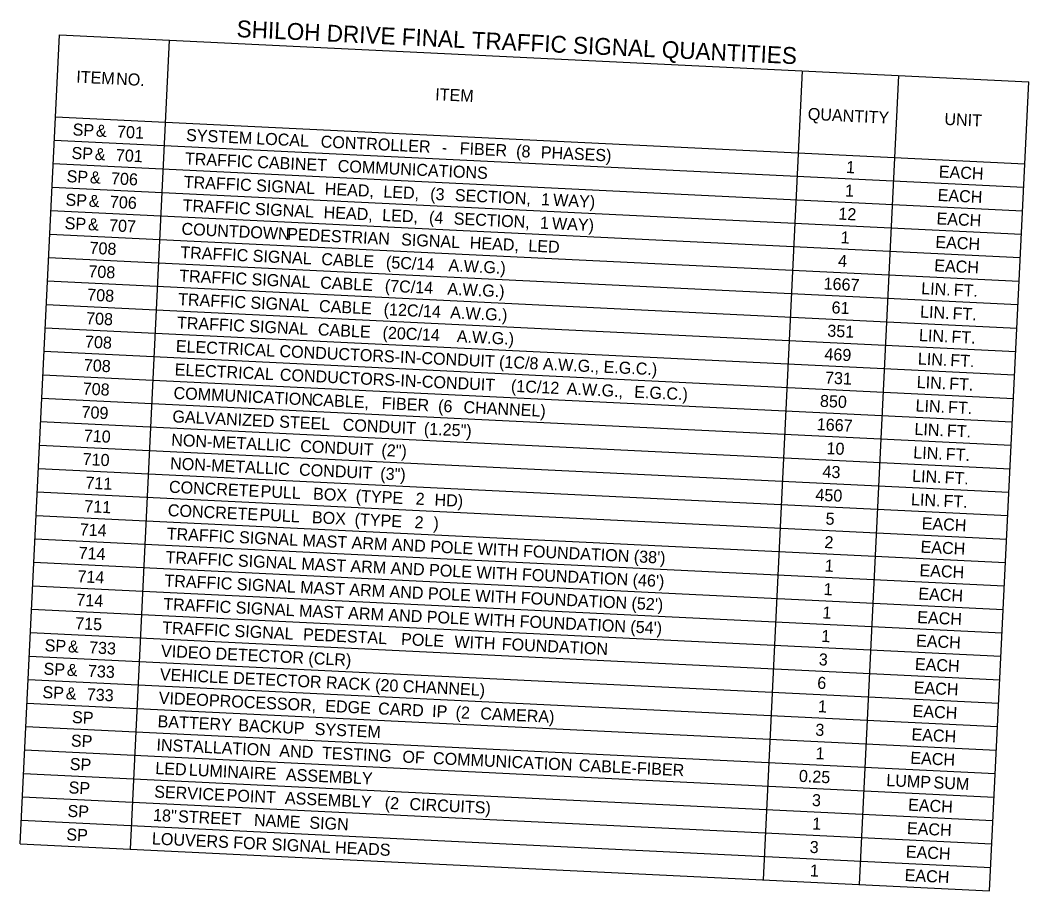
# Model space of a CAD drawing. Extents: x 661018 to 663325, y 642537 to 643074.
# Drawn here: x 661251.9 to 661454.9, y 642806.7 to 642981.8 of the extents above; entities that cross this region are included whole.
import ezdxf

# ---------------------------------------------------------------- set-up
doc = ezdxf.new("R2010")
doc.units = 0
doc.layers.add('R_Border Notes', color=7, linetype='Continuous')

msp = doc.modelspace()

# ---------------------------------------------------------------- linework, layer by layer
at = {"layer": 'R_Border Notes'}
for p, q in [((661251.88, 642816.15), (661259.78, 642978.89)), ((661259.78, 642978.89), (661454.87, 642969.42)), ((661274.05, 642815.08), (661281.95, 642977.81)), ((661401.45, 642808.89), (661409.35, 642971.63)), ((661420.79, 642807.95), (661428.69, 642970.69)), ((661446.97, 642806.68), (661454.87, 642969.42)), ((661258.98, 642962.38), (661454.07, 642952.91)), ((661258.75, 642957.66), (661453.84, 642948.19)), ((661258.52, 642952.95), (661453.61, 642943.47)), ((661258.29, 642948.23), (661453.38, 642938.76)), ((661258.06, 642943.51), (661453.15, 642934.04)), ((661257.83, 642938.79), (661452.92, 642929.32)), ((661257.6, 642934.08), (661452.69, 642924.6)), ((661257.37, 642929.36), (661452.46, 642919.89)), ((661257.14, 642924.64), (661452.24, 642915.17)), ((661256.92, 642919.93), (661452.01, 642910.45)), ((661256.69, 642915.21), (661451.78, 642905.74)), ((661256.46, 642910.49), (661451.55, 642901.02)), ((661256.23, 642905.78), (661451.32, 642896.3)), ((661256, 642901.06), (661451.09, 642891.58)), ((661255.77, 642896.34), (661450.86, 642886.87)), ((661255.54, 642891.62), (661450.63, 642882.15)), ((661255.31, 642886.91), (661450.4, 642877.43)), ((661255.08, 642882.19), (661450.17, 642872.72)), ((661254.85, 642877.47), (661449.94, 642868)), ((661254.63, 642872.76), (661449.72, 642863.28)), ((661254.4, 642868.04), (661449.49, 642858.57)), ((661254.17, 642863.32), (661449.26, 642853.85)), ((661253.94, 642858.61), (661449.03, 642849.13)), ((661253.71, 642853.89), (661448.8, 642844.41)), ((661253.48, 642849.17), (661448.57, 642839.7)), ((661253.25, 642844.45), (661448.34, 642834.98)), ((661253.02, 642839.74), (661448.11, 642830.26)), ((661252.79, 642835.02), (661447.88, 642825.55)), ((661252.56, 642830.3), (661447.65, 642820.83)), ((661252.33, 642825.59), (661447.43, 642816.11)), ((661252.11, 642820.87), (661447.2, 642811.4)), ((661251.88, 642816.15), (661446.97, 642806.68))]:
    msp.add_line(p, q, dxfattribs=at)

# ---------------------------------------------------------------- texts
for s, height, p in [('SHILOH DRIVE FINAL TRAFFIC SIGNAL QUANTITIES', 3.3906, (661295.38, 642978.42)), ('ITEM', 2.422, (661263.12, 642969.24)), (' NO.', 2.422, (661270.24, 642968.89)), ('ITEM', 2.422, (661335.36, 642965.73)), ('QUANTITY', 2.422, (661410.34, 642961.78)), ('UNIT', 2.422, (661437.83, 642960.76)), ('SP', 2.422, (661262.39, 642958.64)), (' &', 2.422, (661266.18, 642958.45)), (' 701', 2.422, (661270.43, 642958.25)), ('SYSTEM', 2.422, (661285.22, 642957.53)), (' LOCAL', 2.422, (661298.44, 642956.89)), (' CONTROLLER', 2.4218, (661311.41, 642956.26)), (' FIBER', 2.422, (661339.39, 642954.9)), (' (8', 2.422, (661350.74, 642954.35)), (' PHASES)', 2.422, (661355.71, 642954.11)), ('SP', 2.422, (661262.16, 642953.92)), (' &', 2.422, (661265.96, 642953.74)), (' 701', 2.422, (661270.2, 642953.53)), ('TRAFFIC', 2.422, (661284.99, 642952.81)), (' CABINET', 2.422, (661298.65, 642952.15)), (' -', 2.422, (661335.79, 642955.07)), (' COMMUNICATIONS', 2.4218, (661314.84, 642951.36)), ('1', 2.42, (661418.05, 642951.08)), ('EACH', 2.422, (661436.71, 642950.17)), ('SP', 2.422, (661261.18, 642949.24)), (' &', 2.422, (661264.97, 642949.06)), (' 706', 2.422, (661269.22, 642948.85)), ('TRAFFIC', 2.422, (661284.76, 642948.1)), (' SIGNAL', 2.422, (661298.42, 642947.43)), (' HEAD,', 2.422, (661312.23, 642946.76)), (' LED,', 2.422, (661324.02, 642946.19)), ('1', 2.42, (661417.82, 642946.36)), ('SP', 2.422, (661260.95, 642944.52)), (' &', 2.422, (661264.74, 642944.34)), (' 706', 2.422, (661268.99, 642944.13)), (' (3', 2.422, (661333.45, 642945.73)), (' SECTION,', 2.422, (661338.42, 642945.49)), (' 1', 2.422, (661355.77, 642944.65)), (' WAY)', 2.422, (661358.19, 642944.53)), ('EACH', 2.422, (661436.48, 642945.46)), ('TRAFFIC', 2.422, (661284.53, 642943.38)), (' SIGNAL', 2.422, (661298.19, 642942.71)), (' HEAD,', 2.422, (661312, 642942.04)), ('SP', 2.422, (661260.79, 642939.8)), (' LED,', 2.422, (661323.79, 642941.47)), (' (4', 2.422, (661333.22, 642941.01)), (' SECTION,', 2.422, (661338.19, 642940.77)), (' 1', 2.422, (661355.54, 642939.93)), ('12', 2.422, (661416.5, 642941.7)), ('EACH', 2.422, (661436.25, 642940.74)), (' &', 2.422, (661264.58, 642939.62)), (' 707', 2.422, (661268.83, 642939.41)), ('COUNTDOWN', 2.422, (661284.3, 642938.66)), (' WAY)', 2.422, (661357.96, 642939.81)), (' PEDESTRIAN', 2.4218, (661304.66, 642937.67)), (' SIGNAL', 2.422, (661327.6, 642936.56)), (' HEAD,', 2.422, (661341.41, 642935.89)), ('1', 2.42, (661416.96, 642936.95)), ('EACH', 2.422, (661436.02, 642936.02)), ('708', 2.422, (661265.79, 642934.83)), ('TRAFFIC', 2.422, (661284.07, 642933.94)), (' LED', 2.422, (661353.2, 642935.32)), (' SIGNAL', 2.422, (661297.73, 642933.28)), (' CABLE', 2.422, (661311.54, 642932.61)), (' (5C/14', 2.422, (661324.55, 642931.98)), ('4', 2.42, (661416.44, 642932.24)), ('708', 2.422, (661265.56, 642930.11)), (' A.W.G.)', 2.422, (661337.14, 642931.37)), ('EACH', 2.422, (661435.79, 642931.3)), ('TRAFFIC', 2.422, (661283.84, 642929.23)), (' SIGNAL', 2.422, (661297.5, 642928.56)), (' CABLE', 2.422, (661311.31, 642927.89)), ('1667', 2.422, (661413.53, 642927.66)), (' (7C/14', 2.422, (661324.32, 642927.26)), (' A.W.G.)', 2.422, (661336.91, 642926.65)), ('LIN.', 2.422, (661433.17, 642926.7)), (' FT.', 2.422, (661438.81, 642926.43)), ('708', 2.422, (661265.33, 642925.4)), ('TRAFFIC', 2.422, (661283.62, 642924.51)), (' SIGNAL', 2.422, (661297.27, 642923.85)), (' CABLE', 2.422, (661311.08, 642923.18)), (' (12C/14', 2.422, (661324.09, 642922.54)), (' A.W.G.)', 2.422, (661337.48, 642921.89)), ('61', 2.422, (661415.13, 642922.85)), ('LIN.', 2.422, (661432.94, 642921.99)), (' FT.', 2.422, (661438.58, 642921.71)), ('708', 2.422, (661265.1, 642920.68)), ('TRAFFIC', 2.422, (661283.39, 642919.79)), (' SIGNAL', 2.422, (661297.04, 642919.13)), (' CABLE', 2.422, (661310.85, 642918.46)), (' (20C/14', 2.422, (661323.86, 642917.83)), ('351', 2.422, (661414.27, 642918.17)), ('708', 2.422, (661264.88, 642915.96)), (' A.W.G.)', 2.422, (661338.81, 642917.1)), ('LIN.', 2.422, (661432.72, 642917.27)), (' FT.', 2.422, (661438.35, 642917)), ('ELECTRICAL CONDUCTORS-IN-CONDUIT (1C/8 A.W.G., E.G.C.)', 2.4218, (661283.16, 642915.08)), ('469', 2.422, (661413.69, 642913.47)), ('LIN.', 2.422, (661432.49, 642912.55)), (' FT.', 2.422, (661438.12, 642912.28)), ('708', 2.422, (661264.65, 642911.25)), ('ELECTRICAL', 2.422, (661282.93, 642910.36)), (' CONDUCTORS-IN-CONDUIT', 2.4218, (661303.19, 642909.37)), ('731', 2.422, (661413.81, 642908.73)), ('LIN.', 2.422, (661432.26, 642907.84)), (' FT.', 2.422, (661437.9, 642907.56)), ('708', 2.422, (661264.42, 642906.53)), ('COMMUNICATION', 2.4218, (661282.7, 642905.64)), (' (1C/12', 2.422, (661349.71, 642907.12)), (' A.W.G.,', 2.422, (661360.93, 642906.57)), (' E.G.C.)', 2.422, (661374.51, 642905.91)), (' CABLE,', 2.422, (661309.61, 642904.33)), (' FIBER', 2.422, (661323.69, 642903.65)), ('850', 2.422, (661412.79, 642904.05)), ('709', 2.422, (661264.18, 642901.81)), (' (6', 2.422, (661335.04, 642903.1)), (' CHANNEL)', 2.422, (661340.15, 642902.85)), ('LIN.', 2.422, (661432.03, 642903.12)), (' FT.', 2.422, (661437.67, 642902.84)), ('GALVANIZED', 2.422, (661282.47, 642900.92)), (' STEEL', 2.422, (661303.06, 642899.92)), (' CONDUIT', 2.422, (661315.84, 642899.3)), ('1667', 2.422, (661412.15, 642899.36)), (' (1.25")', 2.422, (661332.18, 642898.51)), ('LIN.', 2.422, (661431.8, 642898.4)), (' FT.', 2.422, (661437.44, 642898.13)), ('710', 2.422, (661264.64, 642897.06)), ('NON-METALLIC', 2.4218, (661282.24, 642896.21)), (' CONDUIT', 2.422, (661307.29, 642894.99)), (' (2")', 2.422, (661323.63, 642894.2)), ('10', 2.422, (661414.11, 642894.53)), ('LIN.', 2.422, (661431.57, 642893.68)), (' FT.', 2.422, (661437.21, 642893.41)), ('710', 2.422, (661264.41, 642892.35)), ('NON-METALLIC', 2.4218, (661282.01, 642891.49)), (' CONDUIT', 2.422, (661307.06, 642890.27)), (' (3")', 2.422, (661323.4, 642889.48)), ('43', 2.422, (661413.3, 642889.84)), ('711', 2.422, (661264.97, 642887.59)), ('LIN.', 2.422, (661431.34, 642888.97)), (' FT.', 2.422, (661436.98, 642888.69)), ('CONCRETE', 2.422, (661281.78, 642886.77)), (' PULL', 2.422, (661299.31, 642885.92)), (' BOX', 2.422, (661309.88, 642885.41)), (' (TYPE', 2.422, (661318.47, 642884.99)), ('450', 2.422, (661411.88, 642885.18)), (' 2', 2.422, (661330.52, 642884.41)), (' HD)', 2.422, (661334.32, 642884.22)), ('LIN.', 2.422, (661431.11, 642884.25)), (' FT.', 2.422, (661436.75, 642883.98)), ('711', 2.422, (661264.74, 642882.87)), ('CONCRETE', 2.422, (661281.55, 642882.06)), (' PULL', 2.422, (661299.08, 642881.21)), (' BOX', 2.422, (661309.65, 642880.69)), (' (TYPE', 2.422, (661318.24, 642880.28)), (' 2', 2.422, (661330.3, 642879.69)), (' )', 2.422, (661334.09, 642879.51)), ('5', 2.42, (661413.92, 642880.36)), ('EACH', 2.422, (661433.27, 642879.42)), ('714', 2.422, (661263.82, 642878.19)), ("TRAFFIC SIGNAL MAST ARM AND POLE WITH FOUNDATION (38')", 2.4218, (661281.33, 642877.34)), ('2', 2.42, (661413.69, 642875.64)), ('714', 2.422, (661263.59, 642873.47)), ('EACH', 2.422, (661433.04, 642874.7)), ("TRAFFIC SIGNAL MAST ARM AND POLE WITH FOUNDATION (46')", 2.4218, (661281.1, 642872.62)), ('1', 2.42, (661413.75, 642870.91)), ('714', 2.422, (661263.37, 642868.76)), ('EACH', 2.422, (661432.82, 642869.98)), ("TRAFFIC SIGNAL MAST ARM AND POLE WITH FOUNDATION (52')", 2.4218, (661280.87, 642867.91)), ('1', 2.42, (661413.52, 642866.19)), ('EACH', 2.422, (661432.59, 642865.27)), ('714', 2.422, (661263.14, 642864.04)), ("TRAFFIC SIGNAL MAST ARM AND POLE WITH FOUNDATION (54')", 2.4218, (661280.64, 642863.19)), ('1', 2.42, (661413.29, 642861.48)), ('715', 2.422, (661262.91, 642859.32)), ('EACH', 2.422, (661432.36, 642860.55)), ('TRAFFIC', 2.422, (661280.41, 642858.47)), (' SIGNAL', 2.422, (661294.07, 642857.81)), (' PEDESTAL', 2.422, (661307.87, 642857.14)), ('1', 2.42, (661413.06, 642856.76)), ('SP', 2.422, (661256.76, 642854.89)), (' &', 2.422, (661260.55, 642854.71)), (' POLE', 2.422, (661327.59, 642856.18)), (' WITH', 2.422, (661338.31, 642855.66)), (' FOUNDATION', 2.4218, (661347.85, 642855.2)), ('EACH', 2.422, (661432.13, 642855.83)), (' 733', 2.422, (661264.8, 642854.5)), ('VIDEO DETECTOR (CLR)', 2.4218, (661280.18, 642853.75)), ('3', 2.42, (661412.55, 642852.05)), ('EACH', 2.422, (661431.9, 642851.12)), ('SP', 2.422, (661256.54, 642850.17)), (' &', 2.422, (661260.33, 642849.99)), (' 733', 2.422, (661264.57, 642849.78)), ('VEHICLE DETECTOR RACK (20 CHANNEL)', 2.4218, (661279.95, 642849.04)), ('6', 2.42, (661412.25, 642847.34)), ('SP', 2.422, (661256.31, 642845.46)), (' &', 2.422, (661260.1, 642845.27)), (' 733', 2.422, (661264.34, 642845.07)), ('EACH', 2.422, (661431.67, 642846.4)), ('VIDEO', 2.422, (661279.72, 642844.32)), (' PROCESSOR,', 2.4218, (661288.92, 642843.87)), (' EDGE', 2.422, (661312.33, 642842.74)), ('1', 2.42, (661412.38, 642842.61)), ('SP', 2.422, (661262.27, 642840.44)), (' CARD', 2.422, (661322.98, 642842.22)), (' IP', 2.422, (661333.83, 642841.69)), (' (2', 2.422, (661338.56, 642841.46)), (' CAMERA)', 2.422, (661343.53, 642841.22)), ('EACH', 2.422, (661431.44, 642841.68)), ('BATTERY', 2.422, (661279.49, 642839.6)), (' BACKUP', 2.422, (661294.84, 642838.86)), (' SYSTEM', 2.422, (661310.2, 642838.11)), ('3', 2.42, (661411.86, 642837.9)), ('EACH', 2.422, (661431.21, 642836.96)), ('SP', 2.422, (661262.04, 642835.72)), ('INSTALLATION', 2.4218, (661279.26, 642834.89)), (' AND', 2.422, (661303.09, 642833.73)), (' TESTING', 2.422, (661311.66, 642833.31)), (' OF', 2.422, (661327.85, 642832.53)), ('1', 2.42, (661411.92, 642833.17)), ('EACH', 2.422, (661430.98, 642832.25)), ('SP', 2.422, (661261.81, 642831.01)), (' COMMUNICATION', 2.4218, (661334.02, 642832.23)), (' CABLE-FIBER', 2.4218, (661363.36, 642830.8)), ('LED', 2.422, (661279.03, 642830.17)), (' LUMINAIRE', 2.422, (661284.88, 642829.89)), (' ASSEMBLY', 2.422, (661304.41, 642828.94)), ('0.25', 2.422, (661408.55, 642828.61)), ('SP', 2.422, (661261.58, 642826.29)), ('LUMP', 2.422, (661426.14, 642827.75)), (' SUM', 2.422, (661434.74, 642827.34)), ('SERVICE', 2.422, (661278.81, 642825.45)), (' POINT', 2.422, (661292.48, 642824.79)), (' ASSEMBLY', 2.422, (661304.21, 642824.22)), (' (2', 2.422, (661324.31, 642823.24)), (' CIRCUITS)', 2.422, (661329.28, 642823)), ('3', 2.42, (661411.18, 642823.75)), ('EACH', 2.422, (661430.53, 642822.81)), ('SP', 2.422, (661261.35, 642821.57)), ('18"', 2.422, (661278.58, 642820.74)), (' STREET', 2.422, (661282.71, 642820.53)), (' NAME', 2.422, (661297.99, 642819.79)), (' SIGN', 2.422, (661309.13, 642819.25)), ('1', 2.42, (661411.23, 642819.02)), ('EACH', 2.422, (661430.3, 642818.1)), ('SP', 2.422, (661261.12, 642816.85)), ('LOUVERS FOR SIGNAL HEADS', 2.4218, (661278.35, 642816.02)), ('3', 2.42, (661410.72, 642814.32)), ('EACH', 2.422, (661430.07, 642813.38)), ('1', 2.42, (661410.77, 642809.59)), ('EACH', 2.422, (661429.84, 642808.66))]:
    msp.add_text(s, height=height, rotation=357.2199, dxfattribs=at).set_placement(p)

doc.saveas('drawing.dxf')
